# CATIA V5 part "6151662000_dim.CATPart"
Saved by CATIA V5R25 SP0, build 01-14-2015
Part number: 6151662000_dim
Source: made
Property "PROI_CREATED_ON": "12/17/2008 9:21:37 AM"
Property "BLANK_DRAWING": "--"
Property "DRAWN_BY": "FPA"
Property "FINISH": "--"
Property "HEAT_TREATMENT": "ASSIGN"
Property "MATERIAL": "ASSIGN"
Property "PROJECT": "--"
Property "PROTOTYPE_NO": "--"
Property "RELATED_DRAWING": "--"
Property "COMPLETE_MATERIAL": "ASSIGN-ASSIGN"
Property "DESCRIPTION": "ERP30"
Property "DRAWING_EXIST": "--"
Property "MANUFACTURER": "--"
Property "MANUFACTURER_2": "--"
Property "MANUFACTURER_REF": "--"
Property "TYPE_PART": "--"
Property "TODAY_DATE": "2021/07/23"
Property "PDMREV": "01.0"
Property "PDMRL": "Production"
Property "PROI_REVISION": "01"
Property "PROI_VERSION": "0"
Property "PROI_RELEASE": "Production"
Property "PTC_MODIFIED": false
Property "MFG_WP_MATERIAL": "ASSIGN"
Property "COMPANY_CODE": "---"
Property "DESCRIPTION_JP": "--"
Property "PQP_DOCUMENT": "--"
Property "GHOST": false
Property "NO_PART": false
Property "PTC_WM_ITERATION": "0"
Property "PTC_WM_VERSION": "01.0"
Property "PTC_WM_CREATED_ON": "23-Jul-21 01:40:05 PM"
Property "PTC_WM_MODIFIED_ON": "23-Jul-21 01:43:01 PM"
Property "PTC_WM_NAME": "6151662000_dim.prt"
Property "PTC_WM_NUMBER": "6151662000_DIM.PRT"
Property "PTC_WM_LIFECYCLE_STATE": "Production"
Property "PTC_WM_LIFECYCLE": "Design_Process"
Property "PTC_WM_REVISION": "01"
Property "PTC_WM_CREATED_BY": "Florian Pavageau (Grefpav) (Grefpav: CPD)"
Property "PTC_WM_MODIFIED_BY": "Florian Pavageau (Grefpav) (Grefpav: CPD)"
Property "PTC_ORGANIZATION_ID": "CPD"
Property "PTC_WM_LOCATION": "/Products/ELECTRIC EB TOOLS/038-PISTOL GRIP ERP-ECP/9-01-Dimensional Drawings an"
Property "PTC_WM_PART_NAME": "6151662000_dim.prt"
Property "PTC_WM_PART_NUMBER": "6151662000_DIM"
Property "PTC_WM_TEAM": "Default"
Property "EXPORT_CONTROL": "NULL"
Property "PTC_COMMON_NAME": "6151662000_dim.prt"
Property "PTC_MASTER_MATERIAL": "ASSIGN"
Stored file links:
  d:\ptc\Echange\temp\6151662000_dim.CATPart

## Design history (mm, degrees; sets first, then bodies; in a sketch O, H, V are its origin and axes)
AxisSystem1 "CS0": origin (0, 0, 0), X (1, 0, 0), Y (0, 1, 0), Z (0, 0, 1)
Set1
  DatumSurface1 "Sheet.1"
  DatumSurface2 "Sheet.2"
  DatumSurface3 "Sheet.3"
  DatumSurface4 "Sheet.4"
  DatumSurface5 "Sheet.5"
  DatumSurface6 "Sheet.6"
  DatumSurface7 "Sheet.7"
  DatumSurface8 "Sheet.8"
  DatumSurface9 "Sheet.9"
  DatumSurface10 "Sheet.10"
  DatumSurface11 "Sheet.11"
  DatumSurface12 "Sheet.12"
  DatumSurface13 "Sheet.13"
  DatumSurface14 "Sheet.14"
  DatumSurface15 "Sheet.15"
  DatumSurface16 "Sheet.16"
  DatumSurface17 "Sheet.17"
  DatumSurface18 "Sheet.18"
  DatumSurface19 "Sheet.19"
  DatumSurface20 "Sheet.20"
  DatumSurface21 "Sheet.21"
  DatumSurface22 "Sheet.22"
  DatumSurface23 "Sheet.23"
  DatumSurface24 "Sheet.24"
  DatumSurface25 "Sheet.25"
  DatumSurface26 "Sheet.26"
  DatumSurface27 "Sheet.27"
  DatumSurface28 "Sheet.28"
  DatumSurface29 "Sheet.29"
  DatumSurface30 "Sheet.30"
  DatumSurface31 "Sheet.31"
  DatumSurface32 "Sheet.32"
  Plane1 "RIGHT": stored without definition
  Plane2 "TOP": stored without definition
  Plane3 "FRONT": stored without definition
  Line1 "A_1": stored without definition
  Line2 "A_3": stored without definition
Body1 "PartBody" (main body)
